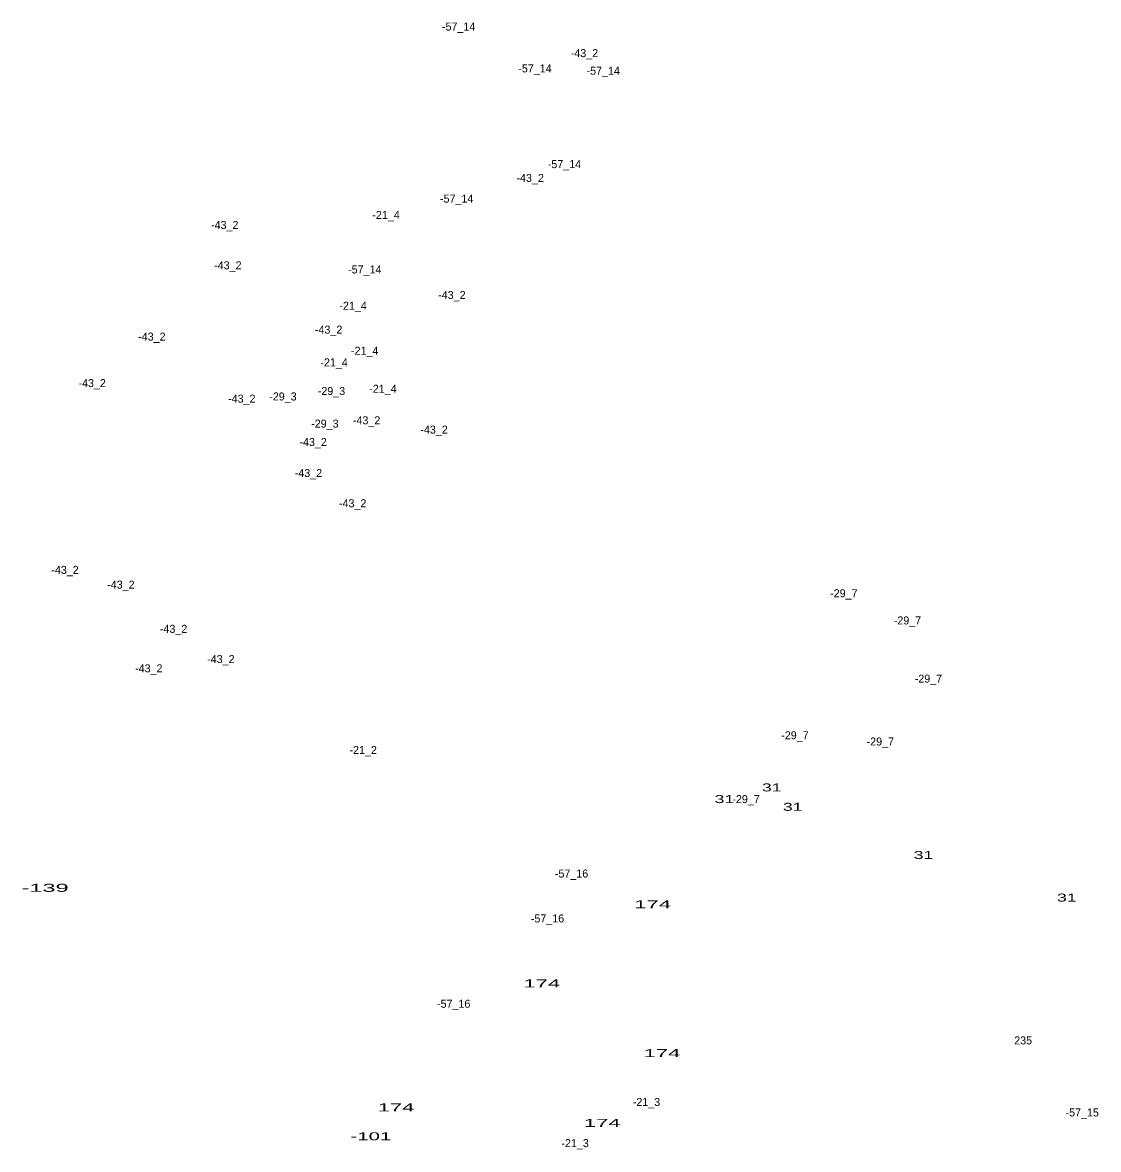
# Model space of a CAD drawing. Extents: x -656096 to -652763, y -1002270 to -998958.
# Drawn here: x -654607 to -654069, y -999843 to -999280 of the extents above; entities that cross this region are included whole.
import ezdxf
from ezdxf.enums import TextEntityAlignment as Align

# ---------------------------------------------------------------- set-up
doc = ezdxf.new("R2010")
doc.units = 0
doc.header["$LTSCALE"] = 1.6
doc.layers.add('24', color=7, linetype='Continuous')

msp = doc.modelspace()

# ---------------------------------------------------------------- texts
at = {"layer": '24'}
for s, p in [('-57_14', (-654388.906, -999283.7)), ('-43_2', (-654326.037, -999296.99)), ('-57_14', (-654350.756, -999304.62)), ('-57_14', (-654316.676, -999305.78)), ('-57_14', (-654336.036, -999352.46)), ('-43_2', (-654353.147, -999359.37)), ('-57_14', (-654389.866, -999369.69)), ('-21_4', (-654425.15, -999377.86)), ('-43_2', (-654505.727, -999382.88)), ('-43_2', (-654504.177, -999403.02)), ('-57_14', (-654435.766, -999405.1)), ('-43_2', (-654392.257, -999417.86)), ('-21_4', (-654441.62, -999423.24)), ('-43_2', (-654453.837, -999435.18)), ('-43_2', (-654542.127, -999438.66)), ('-21_4', (-654435.81, -999445.74)), ('-21_4', (-654451.12, -999451.55)), ('-43_2', (-654571.947, -999461.91)), ('-43_2', (-654497.207, -999469.66)), ('-29_3', (-654476.648, -999468.58)), ('-29_3', (-654452.418, -999465.86)), ('-21_4', (-654426.7, -999464.74)), ('-43_2', (-654434.857, -999480.5)), ('-29_3', (-654455.708, -999482.15)), ('-43_2', (-654401.167, -999485.15)), ('-43_2', (-654461.577, -999491.35)), ('-43_2', (-654463.907, -999506.85)), ('-43_2', (-654441.827, -999521.96)), ('-43_2', (-654585.507, -999555.27)), ('-43_2', (-654557.617, -999562.63)), ('-29_7', (-654196.464, -999566.94)), ('-29_7', (-654164.674, -999580.52)), ('-43_2', (-654531.287, -999584.72)), ('-43_2', (-654543.677, -999604.47)), ('-43_2', (-654507.667, -999599.83)), ('-29_7', (-654154.204, -999609.61)), ('-29_7', (-654220.894, -999637.92)), ('-29_7', (-654178.244, -999641.02)), ('-21_2', (-654436.556, -999645.26)), ('-29_7', (-654245.314, -999669.82)), ('-57_16', (-654332.487, -999707.02)), ('-57_16', (-654344.497, -999729.48)), ('-57_16', (-654391.357, -999772.1)), ('235', (-654106.897, -999790.43)), ('-21_3', (-654295.056, -999821.21)), ('-57_15', (-654077.382, -999826.43)), ('-21_3', (-654330.726, -999841.77))]:
    msp.add_text(s, height=4, dxfattribs=at).set_placement(p, align=Align.CENTER)
for s, width, p in [('31', 1.65, (-654232.477, -999663.99)), ('31', 1.65, (-654256.127, -999669.81)), ('31', 1.65, (-654222.007, -999673.68)), ('31', 1.65, (-654156.677, -999697.73)), ('-139', 2.2, (-654595.475, -999714.16)), ('174', 2.05, (-654291.968, -999722.4)), ('31', 1.65, (-654085.077, -999719.04)), ('174', 2.05, (-654347.348, -999761.92)), ('174', 2.05, (-654287.318, -999796.78)), ('174', 2.05, (-654420.158, -999823.9)), ('174', 2.05, (-654317.138, -999831.65)), ('-101', 1.9, (-654432.723, -999838.34))]:
    msp.add_text(s, height=4, dxfattribs=dict(at, width=width)).set_placement(p, align=Align.CENTER)

doc.saveas('drawing.dxf')
